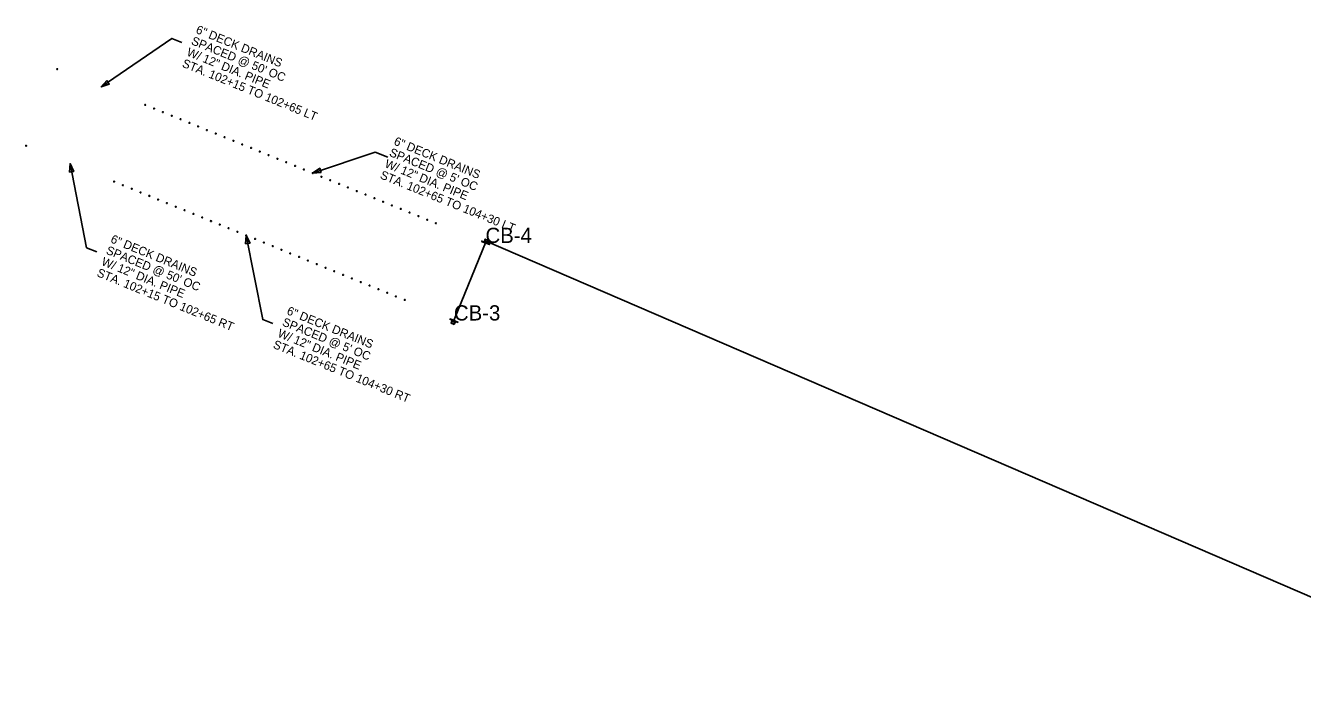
# Model space of a CAD drawing. Extents: x 2165744 to 2171481, y 206867 to 209489.
# Drawn here: x 2170138 to 2170810, y 207180 to 207528 of the extents above; entities that cross this region are included whole.
import ezdxf

# ---------------------------------------------------------------- set-up
doc = ezdxf.new("R2010")
doc.units = 0
for name, color, linetype in [('RD_PD_DR_Inlet', 7, 'Continuous'), ('RD_PD_DR_Inlet_TX', 7, 'Continuous'), ('RD_PD_DR_Pipe', 7, 'Continuous'), ('RD_TX_Drainage', 7, 'Continuous')]:
    doc.layers.add(name, color=color, linetype=linetype)

msp = doc.modelspace()

# ---------------------------------------------------------------- linework, layer by layer
at = {"layer": 'RD_PD_DR_Inlet'}
for p, q in [((2170378.01, 207414.81), (2170378.01, 207414.81)), ((2170379.83, 207415.14), (2170379.83, 207415.14)), ((2170380.07, 207413.97), (2170380.36, 207414.67)), ((2170380.07, 207413.97), (2170380.07, 207413.97)), ((2170380.07, 207413.97), (2170380.07, 207413.97)), ((2170380.13, 207414.12), (2170380.13, 207414.12)), ((2170380.2, 207414.28), (2170380.2, 207414.28)), ((2170380.45, 207414.89), (2170380.45, 207414.89)), ((2170380.7, 207415.51), (2170380.7, 207415.51)), ((2170380.7, 207415.51), (2170380.7, 207415.51)), ((2170381.06, 207414.64), (2170381.06, 207414.64)), ((2170361.42, 207374.05), (2170361.42, 207374.05)), ((2170363.48, 207373.22), (2170363.19, 207372.51)), ((2170363.41, 207373.06), (2170363.41, 207373.06)), ((2170363.48, 207373.22), (2170363.48, 207373.22)), ((2170363.48, 207373.22), (2170363.48, 207373.22)), ((2170362.48, 207372.54), (2170362.48, 207372.54)), ((2170362.85, 207371.67), (2170362.85, 207371.67)), ((2170362.85, 207371.67), (2170362.85, 207371.67)), ((2170363.1, 207372.29), (2170363.1, 207372.29)), ((2170363.35, 207372.91), (2170363.35, 207372.91)), ((2170363.72, 207372.04), (2170363.72, 207372.04))]:
    msp.add_line(p, q, dxfattribs=at)
for points in [[(2170381.58, 207415.33), (2170380.96, 207413.79), (2170382.19, 207413.28), (2170382.13, 207413.13), (2170378.01, 207414.81), (2170378.07, 207414.96), (2170379.31, 207414.46), (2170379.94, 207416)], [(2170380.81, 207414.02), (2170379.58, 207414.53), (2170380.08, 207415.76), (2170381.32, 207415.26)], [(2170363.61, 207371.18), (2170364.24, 207372.73), (2170365.47, 207372.22), (2170365.54, 207372.38), (2170361.42, 207374.05), (2170361.36, 207373.9), (2170362.59, 207373.4), (2170361.96, 207371.85)], [(2170363.97, 207372.66), (2170362.73, 207373.16), (2170362.23, 207371.92), (2170363.47, 207371.42)]]:
    msp.add_lwpolyline(points, close=True, dxfattribs=at)
for centre in [(2170154.91, 207505.37), (2170201.22, 207486.52), (2170205.85, 207484.63), (2170210.49, 207482.74), (2170215.12, 207480.86), (2170219.75, 207478.97), (2170224.38, 207477.09), (2170229.01, 207475.2), (2170233.64, 207473.32), (2170238.27, 207471.43), (2170242.9, 207469.55), (2170247.53, 207467.66), (2170138.51, 207465.08), (2170252.16, 207465.78), (2170256.79, 207463.89), (2170261.42, 207462), (2170266.06, 207460.12), (2170270.69, 207458.23), (2170275.32, 207456.35), (2170279.95, 207454.46), (2170284.58, 207452.58), (2170289.21, 207450.69), (2170293.84, 207448.81), (2170298.47, 207446.92), (2170184.82, 207446.23), (2170189.45, 207444.34), (2170194.08, 207442.46), (2170198.71, 207440.57), (2170303.1, 207445.03), (2170307.73, 207443.15), (2170312.36, 207441.26), (2170203.34, 207438.68), (2170207.97, 207436.8), (2170212.61, 207434.91), (2170317, 207439.38), (2170321.63, 207437.49), (2170326.26, 207435.61), (2170330.89, 207433.72), (2170217.24, 207433.03), (2170221.87, 207431.14), (2170226.5, 207429.26), (2170231.13, 207427.37), (2170335.52, 207431.84), (2170340.15, 207429.95), (2170344.78, 207428.07), (2170235.76, 207425.49), (2170240.39, 207423.6), (2170245.02, 207421.72), (2170249.65, 207419.83), (2170349.41, 207426.18), (2170354.04, 207424.29), (2170254.28, 207417.94), (2170258.91, 207416.06), (2170263.54, 207414.17), (2170268.18, 207412.29), (2170272.81, 207410.4), (2170277.44, 207408.52), (2170282.07, 207406.63), (2170286.7, 207404.75), (2170291.33, 207402.86), (2170295.96, 207400.98), (2170300.59, 207399.09), (2170305.22, 207397.2), (2170309.85, 207395.32), (2170314.48, 207393.43), (2170319.12, 207391.55), (2170323.75, 207389.66), (2170328.38, 207387.78), (2170333.01, 207385.89), (2170337.64, 207384.01)]:
    msp.add_circle(centre, 0.25, dxfattribs=at)
at = {"layer": 'RD_PD_DR_Pipe'}
for p, q in [((2170363.48, 207373.22), (2170380.45, 207414.91)), ((2170380.45, 207414.91), (2170925.55, 207179.85))]:
    msp.add_line(p, q, dxfattribs=at)
at = {"layer": 'RD_TX_Drainage'}
for points in [[(2170220.5, 207519.33), (2170215.19, 207521.49), (2170178.07, 207495.94)], [(2170328.73, 207458.99), (2170322.01, 207461.73), (2170289.19, 207450.73)], [(2170175.68, 207409.27), (2170170.37, 207411.44), (2170161.67, 207455.65)], [(2170268.3, 207371.56), (2170262.99, 207373.73), (2170254.28, 207417.94)]]:
    msp.add_lwpolyline(points, dxfattribs=at)
for points in [[(2170180.99, 207499.37), (2170178.07, 207495.94), (2170182.31, 207497.45)], [(2170161.36, 207451.16), (2170161.67, 207455.65), (2170163.65, 207451.61)], [(2170293.68, 207451.01), (2170289.19, 207450.73), (2170292.94, 207453.21)], [(2170253.98, 207413.45), (2170254.28, 207417.94), (2170256.27, 207413.9)]]:
    msp.add_lwpolyline(points, close=True, dxfattribs=at)

# ---------------------------------------------------------------- texts
at = {"layer": 'RD_PD_DR_Inlet_TX'}
for s, p in [('CB-4', (2170380.07, 207413.97)), ('CB-3', (2170363.48, 207373.22))]:
    msp.add_text(s, height=8, dxfattribs=at).set_placement(p)
at = {"layer": 'RD_TX_Drainage'}
for s, p in [('6" DECK DRAINS', (2170227.43, 207524.41)), ("SPACED @ 50' OC ", (2170225.02, 207518.5)), ('W/ 12" DIA. PIPE ', (2170222.62, 207512.6)), ('STA. 102+15 TO 102+65 LT', (2170220.21, 207506.69)), ('6" DECK DRAINS', (2170331.52, 207465.75)), ("SPACED @ 5' OC ", (2170329.11, 207459.85)), ('W/ 12" DIA. PIPE ', (2170326.71, 207453.94)), ('STA. 102+65 TO 104+30 LT', (2170324.3, 207448.04)), ('6" DECK DRAINS', (2170182.61, 207414.35)), ('W/ 12" DIA. PIPE ', (2170177.8, 207402.54)), ("SPACED @ 50' OC ", (2170180.2, 207408.44)), ('STA. 102+15 TO 102+65 RT', (2170175.39, 207396.64)), ('6" DECK DRAINS', (2170275.22, 207376.64)), ("SPACED @ 5' OC ", (2170272.82, 207370.73)), ('W/ 12" DIA. PIPE ', (2170270.42, 207364.83)), ('STA. 102+65 TO 104+30 RT', (2170268.01, 207358.93))]:
    msp.add_text(s, height=4.5, rotation=337.83882, dxfattribs=at).set_placement(p)

doc.saveas('drawing.dxf')
